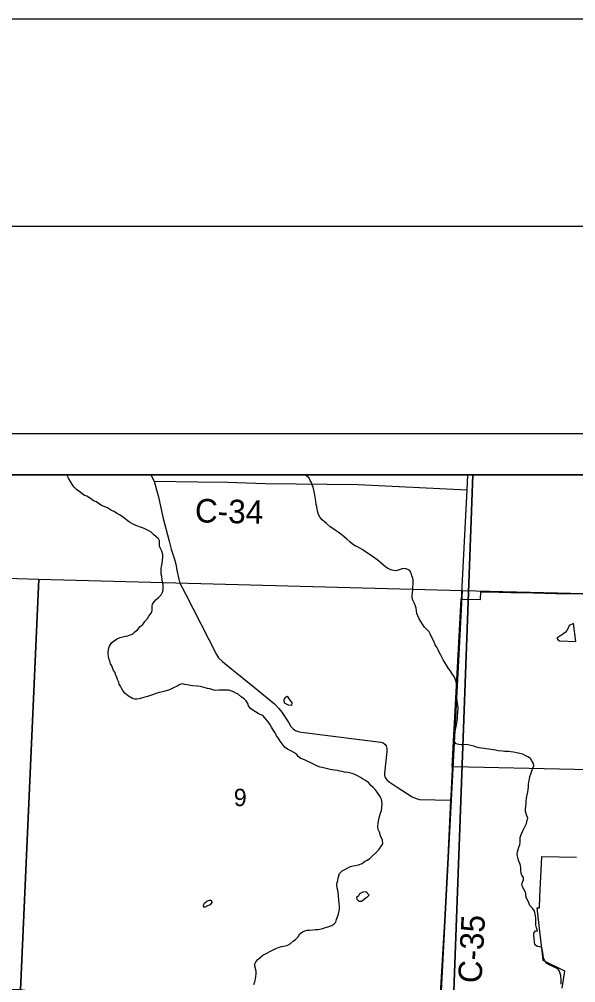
# Model space of a CAD drawing. Extents: x -7.5 to 26.5, y 3.5 to 25.5.
# Drawn here: x -3.216 to -1.873, y 23.173 to 25.5 of the extents above; entities that cross this region are included whole.
import ezdxf

# ---------------------------------------------------------------- set-up
doc = ezdxf.new("R2010")
doc.units = 0
for name, color, linetype in [('GM_X_Corporation', 7, 'Continuous'), ('GM_X_County_Road', 7, 'Continuous'), ('GM_X_County_Road_Text', 7, 'Continuous'), ('GM_X_Minor_River', 7, 'Continuous'), ('GM_X_Section_Text', 7, 'Continuous'), ('SH_Border', 7, 'Continuous'), ('SH_Cut_Line', 7, 'Continuous'), ('SH_Data', 7, 'Continuous')]:
    doc.layers.add(name, color=color, linetype=linetype)

msp = doc.modelspace()

# ---------------------------------------------------------------- linework, layer by layer
at = {"layer": 'GM_X_Corporation'}
for points in [[(1.4431, 17.6), (1.4431, 24.4), (-5.1194, 24.4)], [(-3.3166, 19.1895), (-2.696, 19.1768), (-2.693, 19.1768), (-2.3401, 19.1651), (-2.3128, 19.1642), (-2.2728, 20.2496), (-2.265, 20.4395), (-2.2643, 20.4572), (-2.2393, 21.1622), (-2.2218, 21.6412), (-2.2048, 22.1084), (-2.1854, 22.6407), (-2.1684, 23.1064), (-2.1683, 23.1094), (-2.1213, 24.4), (-5.1194, 24.4)], [(1.4431, 22.0759), (1.4431, 24.4), (-2.1213, 24.4), (-2.1683, 23.1094)], [(-1.8232, 23.6874), (-1.8755, 23.6886), (-2.1675, 23.6951), (-2.1713, 23.6952), (-2.1535, 24.025), (-2.1495, 24.1), (-2.1457, 24.0999), (-2.1026, 24.0989), (-2.1015, 24.1175), (-2.0859, 24.1172), (-2.0289, 24.1158), (-1.9747, 24.1149), (-1.9203, 24.1137), (-1.9108, 24.1135), (-1.8553, 24.1123)], [(-1.9054, 23.1601), (-1.8992, 23.201), (-1.951, 23.2268), (-1.9528, 23.2435), (-1.9592, 23.2968), (-1.966, 23.3543), (-1.96, 23.3541), (-1.9589, 23.3808), (-1.9547, 23.4783), (-1.8705, 23.4768)]]:
    msp.add_lwpolyline(points, dxfattribs=at)
for points in [[(-4.138, 24.1781), (-3.1693, 24.148), (-3.2132, 23.1565), (-4.1729, 23.1886)], [(-3.1693, 24.148), (-2.147, 24.1207), (-2.1999, 23.1078), (-3.2023, 23.155), (-3.2132, 23.1565)], [(-2.147, 24.1207), (-0.8988, 24.09), (-0.9286, 23.0807), (-2.1999, 23.1078)]]:
    msp.add_lwpolyline(points, close=True, dxfattribs=at)
at = {"layer": 'GM_X_County_Road'}
for p, q in [((-2.1349, 24.3638), (-2.1328, 24.4)), ((-2.1478, 24.114), (-2.1349, 24.3638)), ((-2.1488, 24.094), (-2.1478, 24.114))]:
    msp.add_line(p, q, dxfattribs=at)
for points in [[(-2.8984, 24.4), (-2.8909, 24.3844), (-2.8852, 24.3636), (-2.8805, 24.3467), (-2.8701, 24.2977), (-2.8545, 24.2394), (-2.8493, 24.2204), (-2.8421, 24.1985), (-2.838, 24.1841), (-2.835, 24.1654), (-2.8311, 24.1476), (-2.8284, 24.1384), (-2.8233, 24.1277), (-2.8154, 24.1129), (-2.7404, 23.9663), (-2.735, 23.958), (-2.7254, 23.9488), (-2.7158, 23.9413), (-2.6987, 23.9277), (-2.6528, 23.89), (-2.6003, 23.8467), (-2.5899, 23.8359), (-2.5825, 23.8267), (-2.5655, 23.8009), (-2.5603, 23.7924), (-2.5542, 23.7857), (-2.5492, 23.7824), (-2.5474, 23.7817)], [(-2.8909, 24.3844), (-2.7853, 24.3833), (-2.7127, 24.3821), (-2.6673, 24.3804), (-2.623, 24.3793), (-2.3977, 24.3766), (-2.1349, 24.3638)], [(-2.17, 23.6949), (-2.1489, 24.093), (-2.1488, 24.094)], [(-2.5474, 23.7817), (-2.5429, 23.7802), (-2.5351, 23.7781), (-2.3946, 23.761), (-2.3429, 23.7541), (-2.3378, 23.7523), (-2.3336, 23.7492), (-2.3306, 23.7452), (-2.3289, 23.7388), (-2.3286, 23.7317), (-2.3346, 23.6793), (-2.3342, 23.6745), (-2.3327, 23.6686), (-2.3288, 23.6631), (-2.323, 23.6583), (-2.3042, 23.6454), (-2.2672, 23.6221), (-2.2583, 23.6185), (-2.2497, 23.6162), (-2.1743, 23.6146)], [(-2.1737, 23.6247), (-2.1703, 23.6889), (-2.17, 23.6949)], [(-2.2008, 23.1201), (-2.1874, 23.3495), (-2.1808, 23.4761), (-2.1743, 23.6146), (-2.1737, 23.6247)]]:
    msp.add_lwpolyline(points, dxfattribs=at)
at = {"layer": 'GM_X_Minor_River'}
for points in [[(-2.8856, 24.2501), (-2.8919, 24.256), (-2.8978, 24.2615), (-2.9049, 24.2655), (-2.9098, 24.2679), (-2.915, 24.27), (-2.9214, 24.2724), (-2.9346, 24.2774), (-2.9444, 24.2823), (-2.95, 24.2855), (-2.9559, 24.2894), (-2.9619, 24.2942), (-2.9682, 24.2993), (-2.9746, 24.3033), (-2.9813, 24.3073), (-2.9873, 24.3117), (-2.9937, 24.3138), (-3.003, 24.3205), (-3.0139, 24.3243), (-3.0188, 24.3263), (-3.0255, 24.3303), (-3.0303, 24.3346), (-3.0356, 24.3363), (-3.0416, 24.3403), (-3.0472, 24.3443), (-3.0535, 24.3483), (-3.0592, 24.3503), (-3.0655, 24.3547), (-3.0726, 24.3606), (-3.0782, 24.3642), (-3.0841, 24.3701), (-3.0881, 24.3755), (-3.0921, 24.3825), (-3.0979, 24.3922), (-3.1012, 24.4)], [(-2.2651, 24.1344), (-2.2649, 24.1397), (-2.2652, 24.1447), (-2.2661, 24.1504), (-2.2683, 24.1562), (-2.2703, 24.1627), (-2.2732, 24.1681), (-2.2781, 24.1716), (-2.2845, 24.1734), (-2.2917, 24.1732), (-2.2986, 24.1708), (-2.3036, 24.169), (-2.3086, 24.1684), (-2.3158, 24.1698), (-2.3211, 24.1715), (-2.326, 24.1739), (-2.3319, 24.1775), (-2.3371, 24.1818), (-2.3434, 24.1873), (-2.349, 24.1924), (-2.3553, 24.1968), (-2.3613, 24.2008), (-2.3691, 24.2067), (-2.3826, 24.2155), (-2.3885, 24.2195), (-2.3938, 24.2227), (-2.3998, 24.2259), (-2.405, 24.2283), (-2.4117, 24.2327), (-2.4181, 24.2378), (-2.4255, 24.2445), (-2.4318, 24.25), (-2.437, 24.2544), (-2.4463, 24.2611), (-2.4534, 24.2659), (-2.459, 24.2699), (-2.4653, 24.2746), (-2.4746, 24.2825), (-2.4794, 24.2861), (-2.4846, 24.2912), (-2.4901, 24.297), (-2.4934, 24.3039), (-2.4951, 24.3097), (-2.4968, 24.317), (-2.4981, 24.3231), (-2.4995, 24.3284), (-2.5004, 24.3364), (-2.5014, 24.3414), (-2.502, 24.3463), (-2.5036, 24.3555), (-2.5053, 24.3628), (-2.5066, 24.37), (-2.5087, 24.3758), (-2.5108, 24.3812), (-2.5137, 24.3862), (-2.5162, 24.3916), (-2.5225, 24.3971), (-2.5274, 24.3995), (-2.5289, 24.4)], [(-2.7105, 23.8795), (-2.7284, 23.8801), (-2.7349, 23.8795), (-2.7433, 23.8794), (-2.749, 23.8803), (-2.7561, 23.8828), (-2.7618, 23.8838), (-2.7675, 23.8858), (-2.7735, 23.8872), (-2.7799, 23.8889), (-2.7868, 23.8895), (-2.7974, 23.8906), (-2.8031, 23.8911), (-2.8106, 23.8929), (-2.8163, 23.8938), (-2.8224, 23.8948), (-2.8289, 23.8934), (-2.8339, 23.8902), (-2.844, 23.8852), (-2.854, 23.8806), (-2.8621, 23.8781), (-2.8702, 23.8757), (-2.8774, 23.8744), (-2.8867, 23.8717), (-2.8924, 23.8696), (-2.907, 23.8647), (-2.9132, 23.863), (-2.9186, 23.8613), (-2.927, 23.8589), (-2.9324, 23.8579), (-2.9377, 23.8581), (-2.9434, 23.8594), (-2.9523, 23.865), (-2.9605, 23.8717), (-2.9653, 23.8772), (-2.9689, 23.8834), (-2.9722, 23.8892), (-2.9751, 23.8942), (-2.9764, 23.8992), (-2.9793, 23.9053), (-2.9807, 23.9107), (-2.9839, 23.9176), (-2.9852, 23.9226), (-2.9885, 23.9276), (-2.9914, 23.9338), (-2.9931, 23.9388), (-2.996, 23.9438), (-2.9981, 23.9495), (-2.9998, 23.956), (-3.0008, 23.9622), (-3.0014, 23.9671), (-3.0016, 23.9724), (-3.0002, 23.9811), (-2.9989, 23.9864), (-2.9938, 23.9938), (-2.9863, 24), (-2.9801, 24.004), (-2.9724, 24.0072), (-2.9663, 24.0089), (-2.9601, 24.0102), (-2.954, 24.0112), (-2.9483, 24.0133), (-2.9432, 24.0154), (-2.9374, 24.0209), (-2.9308, 24.0256), (-2.9244, 24.0334), (-2.9182, 24.0382), (-2.9134, 24.0456), (-2.9071, 24.053), (-2.9035, 24.0586), (-2.8983, 24.066), (-2.8959, 24.072), (-2.8957, 24.0773), (-2.8959, 24.083), (-2.8946, 24.0879), (-2.8906, 24.0935), (-2.8855, 24.099), (-2.8801, 24.1038), (-2.8734, 24.11), (-2.8702, 24.1168), (-2.8692, 24.122), (-2.8687, 24.1285), (-2.8689, 24.1334), (-2.8702, 24.1407), (-2.8712, 24.146), (-2.8725, 24.154), (-2.8734, 24.1597), (-2.8739, 24.1681), (-2.8738, 24.1734), (-2.8732, 24.1787), (-2.8715, 24.1859), (-2.8705, 24.1949), (-2.8699, 24.2002), (-2.8701, 24.2078), (-2.8725, 24.2159), (-2.875, 24.2217), (-2.8775, 24.2278), (-2.8777, 24.2343), (-2.8782, 24.2404), (-2.8804, 24.2457), (-2.8856, 24.2501)], [(-1.9913, 23.6192), (-1.9899, 23.6275), (-1.9886, 23.634), (-1.9876, 23.6392), (-1.987, 23.6468), (-1.9865, 23.6521), (-1.9859, 23.6589), (-1.9846, 23.6653), (-1.9833, 23.671), (-1.9812, 23.6778), (-1.9787, 23.6849), (-1.9762, 23.6913), (-1.9741, 23.6973), (-1.9747, 23.7026), (-1.9787, 23.7092), (-1.9819, 23.7146), (-1.9883, 23.719), (-1.9943, 23.7222), (-2.0007, 23.725), (-2.0075, 23.7268), (-2.0154, 23.7289), (-2.023, 23.7299), (-2.029, 23.7309), (-2.0351, 23.7314), (-2.0442, 23.7321), (-2.0496, 23.7323), (-2.0602, 23.7333), (-2.0666, 23.7347), (-2.0715, 23.736), (-2.0772, 23.7365), (-2.0825, 23.7375), (-2.0886, 23.738), (-2.0935, 23.7393), (-2.1007, 23.7399), (-2.1056, 23.7404), (-2.1124, 23.7426), (-2.1189, 23.7443), (-2.126, 23.7464), (-2.1328, 23.7477), (-2.1385, 23.7483), (-2.1435, 23.7481), (-2.1492, 23.7482), (-2.1549, 23.7488), (-2.1613, 23.7505), (-2.1661, 23.7564), (-2.1678, 23.7617), (-2.1669, 23.7685), (-2.1652, 23.7742), (-2.1638, 23.7798), (-2.1629, 23.7851), (-2.1616, 23.7911), (-2.1607, 23.7972), (-2.1593, 23.8051), (-2.1579, 23.813), (-2.1577, 23.8195), (-2.1572, 23.8244), (-2.1568, 23.8377), (-2.1584, 23.8476), (-2.1593, 23.8548), (-2.1599, 23.8605), (-2.1601, 23.8655), (-2.1603, 23.8708), (-2.1599, 23.8845), (-2.1601, 23.8928), (-2.1614, 23.8997), (-2.1638, 23.907), (-2.1663, 23.9127), (-2.1707, 23.9197), (-2.1762, 23.9275), (-2.1798, 23.9325), (-2.1845, 23.9399), (-2.1885, 23.9465), (-2.1925, 23.9534), (-2.1961, 23.9596), (-2.1994, 23.9658), (-2.2026, 23.9716), (-2.2047, 23.9769), (-2.2083, 23.9835), (-2.212, 23.9897), (-2.2148, 23.9955), (-2.218, 24.0028), (-2.2209, 24.0089), (-2.2234, 24.014), (-2.2266, 24.0205), (-2.2377, 24.0322), (-2.2428, 24.0392), (-2.2468, 24.0454), (-2.2504, 24.052), (-2.2537, 24.0593), (-2.2561, 24.0654), (-2.2575, 24.0712), (-2.258, 24.078), (-2.2594, 24.083), (-2.2623, 24.0888), (-2.2651, 24.0957), (-2.2676, 24.1019), (-2.2678, 24.1083), (-2.2668, 24.1147), (-2.2662, 24.1219), (-2.2656, 24.1295), (-2.2651, 24.1344)], [(-1.9179, 24.0064), (-1.9161, 24.0022), (-1.9116, 23.999), (-1.8726, 23.9972), (-1.8783, 24.0411)], [(-1.8783, 24.0411), (-1.8883, 24.0357), (-1.8907, 24.0293), (-1.8943, 24.024), (-1.8982, 24.0192), (-1.9067, 24.0129), (-1.9105, 24.0108), (-1.9144, 24.0082), (-1.9179, 24.0064)], [(-2.4489, 23.4023), (-2.4495, 23.4095), (-2.4485, 23.4156), (-2.4472, 23.4205), (-2.4459, 23.4265), (-2.4446, 23.4314), (-2.4429, 23.4374), (-2.4363, 23.4433), (-2.4301, 23.4465), (-2.4231, 23.4505), (-2.4169, 23.4537), (-2.41, 23.4554), (-2.405, 23.4563), (-2.3974, 23.458), (-2.3885, 23.4615), (-2.3827, 23.4659), (-2.3761, 23.4691), (-2.3695, 23.4735), (-2.3632, 23.4797), (-2.3554, 23.4874), (-2.3475, 23.4959), (-2.3419, 23.5037), (-2.3388, 23.5086), (-2.3393, 23.5173), (-2.3443, 23.5281), (-2.3466, 23.5373), (-2.3495, 23.5431), (-2.3508, 23.5499), (-2.3494, 23.5594), (-2.3484, 23.5677), (-2.3463, 23.5748), (-2.3438, 23.5827), (-2.342, 23.5895), (-2.3411, 23.5963), (-2.3404, 23.605), (-2.3406, 23.6107), (-2.3416, 23.6164), (-2.3437, 23.6214), (-2.3477, 23.628), (-2.3521, 23.6338), (-2.3569, 23.6397), (-2.3617, 23.6448), (-2.3673, 23.6495), (-2.3724, 23.6561), (-2.3806, 23.6621), (-2.3877, 23.6661), (-2.3925, 23.6693), (-2.3978, 23.6721), (-2.4064, 23.6761), (-2.4121, 23.6786), (-2.4226, 23.6812), (-2.431, 23.6822), (-2.437, 23.6835), (-2.442, 23.6845), (-2.4476, 23.6858), (-2.4548, 23.6868), (-2.4609, 23.6877), (-2.4658, 23.6886), (-2.4749, 23.6904), (-2.4847, 23.693), (-2.4896, 23.6939), (-2.496, 23.6964), (-2.5039, 23.7), (-2.5122, 23.7041), (-2.5215, 23.7086), (-2.5264, 23.7106), (-2.5317, 23.7134), (-2.5366, 23.7147), (-2.5429, 23.7195), (-2.5462, 23.7249), (-2.5537, 23.7293), (-2.5589, 23.7329), (-2.5638, 23.7353), (-2.569, 23.7377), (-2.5746, 23.7417), (-2.5794, 23.7468), (-2.5867, 23.7569), (-2.591, 23.7646), (-2.5955, 23.7697), (-2.5987, 23.777), (-2.6027, 23.7824), (-2.6074, 23.7909), (-2.6117, 23.7979), (-2.6154, 23.8033), (-2.619, 23.8084), (-2.6231, 23.8134), (-2.6279, 23.8185), (-2.6343, 23.8214), (-2.6395, 23.8238), (-2.6526, 23.8318), (-2.6582, 23.8358), (-2.6629, 23.842), (-2.6647, 23.8477), (-2.6683, 23.8543), (-2.6735, 23.8586), (-2.6794, 23.863), (-2.6876, 23.8701), (-2.6932, 23.8725), (-2.6988, 23.8761), (-2.7052, 23.8786), (-2.7105, 23.8795)], [(-2.5662, 23.8436), (-2.5756, 23.8488), (-2.5765, 23.8576), (-2.5737, 23.8628), (-2.5721, 23.8639)], [(-2.5721, 23.8639), (-2.5691, 23.8654), (-2.5643, 23.858), (-2.5581, 23.8491), (-2.559, 23.8427), (-2.5662, 23.8436)], [(-1.9074, 23.1699), (-1.9075, 23.1798), (-1.9087, 23.1908), (-1.91, 23.1958), (-1.9121, 23.2016), (-1.9158, 23.2066), (-1.9244, 23.2111), (-1.9308, 23.2139), (-1.9364, 23.2167), (-1.9424, 23.22), (-1.9479, 23.2277), (-1.95, 23.2335), (-1.9514, 23.2388), (-1.9523, 23.2465), (-1.9539, 23.2541), (-1.9553, 23.2595), (-1.9648, 23.2609), (-1.9715, 23.2649), (-1.9739, 23.2874), (-1.9741, 23.2934), (-1.9701, 23.2983), (-1.9648, 23.2981), (-1.9669, 23.3057), (-1.9689, 23.3126), (-1.969, 23.3218), (-1.9692, 23.3286), (-1.9698, 23.3347), (-1.9714, 23.3431), (-1.9728, 23.3481), (-1.9772, 23.3535), (-1.9831, 23.3601), (-1.9856, 23.3663), (-1.9885, 23.3717), (-1.9913, 23.3775), (-1.9934, 23.3836), (-1.9933, 23.3885), (-1.995, 23.3939), (-1.9979, 23.3997), (-2.0015, 23.4051), (-2.0025, 23.4112), (-2.0012, 23.4165), (-1.9991, 23.4221), (-1.999, 23.4271), (-2.0026, 23.4332), (-2.0044, 23.4382), (-2.0053, 23.444), (-2.0051, 23.45), (-2.0061, 23.4565), (-2.0075, 23.4615), (-2.0096, 23.4669), (-2.0117, 23.4726), (-2.0134, 23.4787), (-2.014, 23.4848), (-2.0131, 23.4897), (-2.0118, 23.4954), (-2.0097, 23.501), (-2.0076, 23.5063), (-2.0071, 23.5127), (-2.0067, 23.5241), (-2.005, 23.5293), (-2.0026, 23.5346), (-2.0001, 23.5402), (-1.9937, 23.5529), (-1.9916, 23.5581), (-1.9899, 23.5657), (-1.9886, 23.571), (-1.9903, 23.5767), (-1.9942, 23.5871), (-1.994, 23.5935), (-1.993, 23.5988), (-1.9924, 23.6079), (-1.9919, 23.6128), (-1.9913, 23.6192)], [(-2.6497, 23.1687), (-2.6472, 23.1758), (-2.6459, 23.1818), (-2.6449, 23.189), (-2.644, 23.1939), (-2.6442, 23.2011), (-2.6476, 23.2134), (-2.6478, 23.2191), (-2.6454, 23.2239), (-2.6407, 23.2291), (-2.6348, 23.2342), (-2.6282, 23.2401), (-2.6216, 23.2433), (-2.6061, 23.2512), (-2.5968, 23.2562), (-2.5891, 23.2594), (-2.583, 23.2607), (-2.5776, 23.2617), (-2.5681, 23.264), (-2.5619, 23.2673), (-2.5552, 23.2735), (-2.549, 23.2779), (-2.5431, 23.2838), (-2.5391, 23.2912), (-2.5324, 23.2963), (-2.527, 23.2988), (-2.5209, 23.3002), (-2.5152, 23.3007), (-2.5076, 23.3009), (-2.5007, 23.3018), (-2.4957, 23.302), (-2.4908, 23.3026), (-2.4842, 23.3043), (-2.4792, 23.3061), (-2.4735, 23.3078), (-2.4685, 23.3092), (-2.4616, 23.3112), (-2.4565, 23.3149), (-2.4522, 23.32), (-2.4501, 23.3264), (-2.4468, 23.3347), (-2.4455, 23.3396), (-2.4441, 23.3464), (-2.4432, 23.3516), (-2.443, 23.3577), (-2.4436, 23.3653), (-2.4445, 23.3722), (-2.4453, 23.3843), (-2.4466, 23.3912), (-2.4472, 23.3969), (-2.4489, 23.4023)], [(-2.3764, 23.3798), (-2.3896, 23.3698), (-2.3953, 23.3696), (-2.4005, 23.3746), (-2.4011, 23.3804), (-2.396, 23.3844), (-2.394, 23.3889)], [(-2.394, 23.3889), (-2.3863, 23.3925), (-2.3791, 23.3935), (-2.3714, 23.3849), (-2.3764, 23.3797)], [(-2.7617, 23.3591), (-2.769, 23.3554), (-2.7719, 23.3589), (-2.7719, 23.3608), (-2.7691, 23.3653)], [(-2.7691, 23.3653), (-2.7637, 23.3701), (-2.7572, 23.3726), (-2.753, 23.3729), (-2.7516, 23.3672), (-2.7555, 23.3612), (-2.7617, 23.3591)]]:
    msp.add_lwpolyline(points, dxfattribs=at)
at = {"layer": 'SH_Border'}
msp.add_lwpolyline([(-5.9569, 25), (26.0431, 25), (26.0431, 4), (-5.9569, 4)], close=True, dxfattribs=at)
at = {"layer": 'SH_Cut_Line'}
msp.add_lwpolyline([(-7.4569, 3.5), (26.5431, 3.5), (26.5431, 25.5), (-7.4569, 25.5)], close=True, dxfattribs=at)
at = {"layer": 'SH_Data'}
for p, q in [((-5.4569, 24.5), (1.5431, 24.5)), ((-5.3569, 24.4), (1.4431, 24.4))]:
    msp.add_line(p, q, dxfattribs=at)

# ---------------------------------------------------------------- texts
at = {"layer": 'GM_X_County_Road_Text'}
for s, rotation, p in [('C-34', 358.6449, (-2.7926, 24.2853)), ('C-35', 86.9152, (-2.1003, 23.1712))]:
    msp.add_text(s, height=0.05682, rotation=rotation, dxfattribs=at).set_placement(p)
at = {"layer": 'GM_X_Section_Text'}
msp.add_text('9', height=0.0419, rotation=0, dxfattribs=at).set_placement((-2.6984, 23.5999))

doc.saveas('drawing.dxf')
